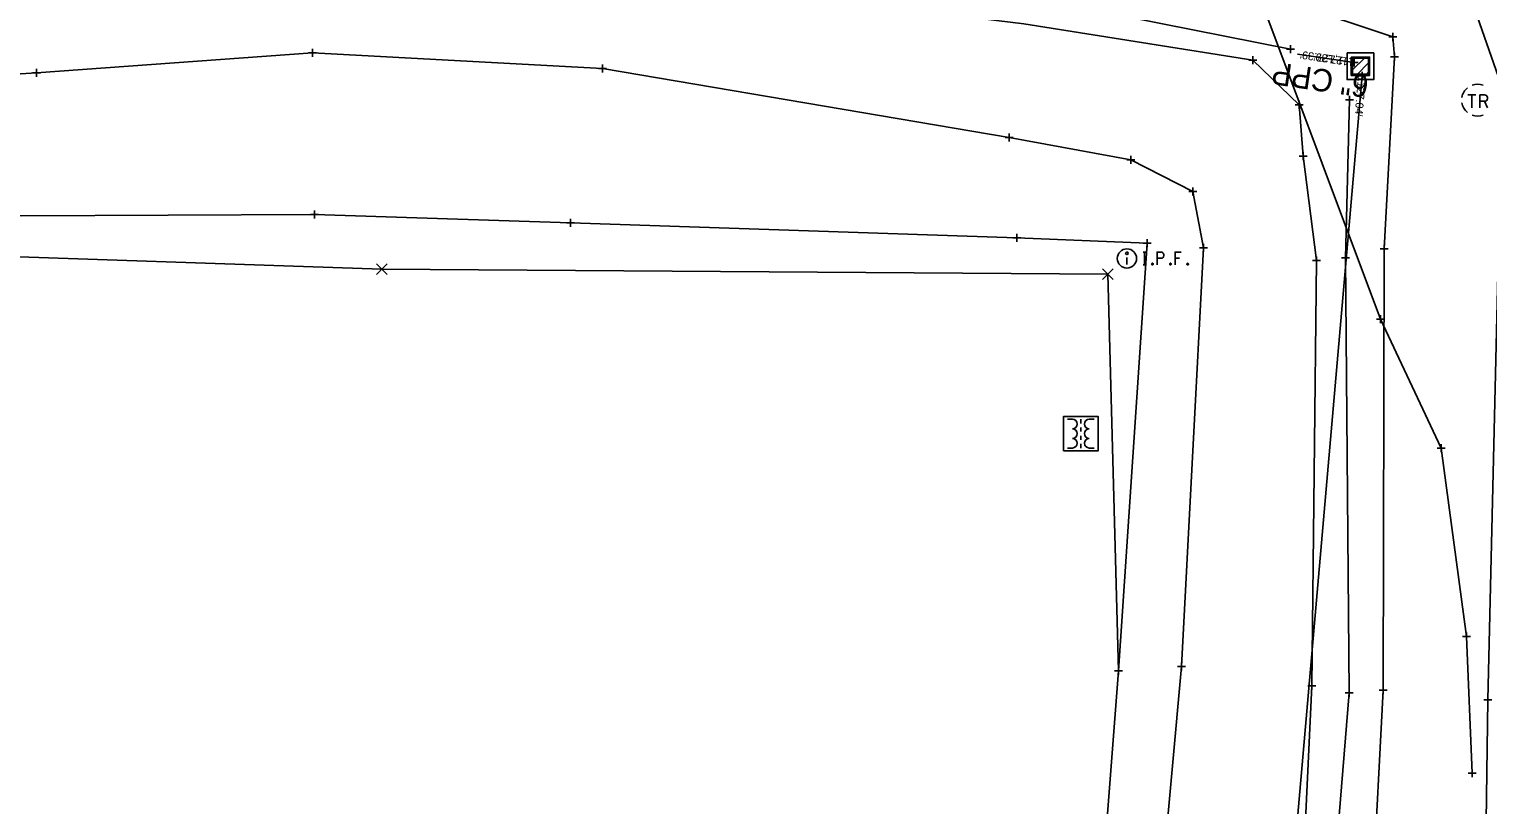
# Model space of a CAD drawing. Extents: x 207090 to 277928, y 600777 to 621109.
# Drawn here: x 260765.1 to 260947.4, y 611469.8 to 611566.6 of the extents above; entities that cross this region are included whole.
import ezdxf

# ---------------------------------------------------------------- set-up
doc = ezdxf.new("R2010")
doc.units = 0
for name, color, linetype in [('ATDIMS', 7, 'Continuous'), ('DR_X_Ditch', 7, 'Continuous'), ('DR_X_Storm_Sewer', 7, 'Continuous'), ('DR_X_Text', 7, 'Continuous'), ('DT_X_Break_Line', 7, 'Continuous'), ('PM_P_Channelizing_Line', 7, 'Continuous'), ('PM_P_Edge_Line', 7, 'Continuous'), ('PM_P_Lane_Line', 7, 'Continuous'), ('PM_P_Stop_Line', 7, 'Continuous'), ('PM_X_Edge_Line', 7, 'Continuous'), ('PM_X_Lane_Line', 7, 'Continuous'), ('PV_X_COP', 7, 'Continuous'), ('SC_ProfileRun1', 7, 'Continuous'), ('SC_ProfileRun2', 7, 'Continuous'), ('SC_ProfileRun4', 7, 'Continuous'), ('SV_X_Terrain_Boundary', 7, 'Continuous'), ('SV_X_Toe_of_Slope', 7, 'Continuous'), ('UT_X_FO', 7, 'Continuous')]:
    doc.layers.add(name, color=color, linetype=linetype)

msp = doc.modelspace()

# ---------------------------------------------------------------- linework, layer by layer
at = {"layer": 'DR_X_Ditch'}
for points in [[(260922.71, 611564.11), (260890.1, 611570.61), (260838.53, 611574.76), (260802.48, 611577.5), (260766.37, 611577.17), (260721.33, 611574.97), (260650.56, 611573.72), (260623.07, 611583.7), (260580.3, 611596.7), (260534.96, 611609.27), (260480.65, 611625.85), (260438.14, 611643.07), (260395.35, 611661.63), (260359.84, 611676.62), (260316.28, 611695.06), (260281.01, 611710.64), (260238.37, 611728.41), (260199.78, 611745.66), (260157.66, 611763.38), (260118.67, 611782.58), (260078.85, 611801.04), (260037.76, 611818.47), (260001.09, 611831.86), (259993.95, 611834.65)], [(260918.27, 611325.53), (260922.87, 611381.19), (260925.97, 611433.7), (260930.02, 611483.73), (260929.59, 611538.06), (260930.07, 611557.8)]]:
    msp.add_lwpolyline(points, dxfattribs=at)
at = {"layer": 'DR_X_Storm_Sewer'}
for p, q in [((260930.64, 611562.44), (260923.59, 611563.47)), ((260931.65, 611560.79), (260881.99, 610991.41))]:
    msp.add_line(p, q, dxfattribs=at)
at = {"layer": 'DT_X_Break_Line'}
msp.add_lwpolyline([(259527, 611849.97), (259626.95, 611842.34), (259741, 611827.05), (259865.07, 611829.81), (259960.08, 611805.1), (260054.94, 611770.89), (260146.45, 611730.46), (260219.24, 611692.26), (260311.2, 611653.27), (260395, 611624.63), (260483.4, 611590.72), (260567.09, 611557.23), (260605.33, 611542.61), (260696.47, 611540.48), (260809.17, 611536.63), (260899.87, 611536.02), (260901.21, 611486.51)], dxfattribs=at)
at = {"layer": 'PM_P_Channelizing_Line'}
msp.add_line((260902.27, 611538.1), (260902.27, 611537.21), dxfattribs=at)
for points in [[(260904.3, 611538.78), (260904.65, 611538.78)], [(260904.47, 611537.18), (260904.47, 611538.78)], [(260906.04, 611537.18), (260906.04, 611538.78), (260906.57, 611538.78), (260906.62, 611538.77), (260906.7, 611538.74), (260906.73, 611538.72), (260906.77, 611538.69), (260906.81, 611538.63), (260906.84, 611538.57), (260906.86, 611538.46), (260906.86, 611538.31), (260906.85, 611538.26), (260906.83, 611538.19), (260906.79, 611538.1), (260906.74, 611538.06), (260906.71, 611538.04), (260906.66, 611538.01), (260906.57, 611538), (260906.04, 611538)], [(260909.05, 611538.78), (260908.29, 611538.78), (260908.29, 611537.18)], [(260904.3, 611537.18), (260904.65, 611537.18)], [(260905.43, 611537.39), (260905.49, 611537.39), (260905.52, 611537.37), (260905.55, 611537.32), (260905.55, 611537.26), (260905.52, 611537.2), (260905.49, 611537.18), (260905.43, 611537.18), (260905.4, 611537.2), (260905.37, 611537.26), (260905.37, 611537.32), (260905.4, 611537.37), (260905.43, 611537.39)], [(260907.68, 611537.39), (260907.74, 611537.39), (260907.77, 611537.37), (260907.8, 611537.32), (260907.8, 611537.26), (260907.77, 611537.2), (260907.74, 611537.18), (260907.68, 611537.18), (260907.65, 611537.2), (260907.61, 611537.26), (260907.61, 611537.32), (260907.65, 611537.37), (260907.68, 611537.39)], [(260908.29, 611538), (260908.83, 611538)], [(260909.83, 611537.39), (260909.89, 611537.39), (260909.92, 611537.37), (260909.95, 611537.32), (260909.95, 611537.26), (260909.92, 611537.2), (260909.89, 611537.18), (260909.83, 611537.18), (260909.8, 611537.2), (260909.76, 611537.26), (260909.76, 611537.32), (260909.8, 611537.37), (260909.83, 611537.39)]]:
    msp.add_lwpolyline(points, dxfattribs=at)
for centre, radius in [((260902.27, 611537.98), 1.2), ((260902.27, 611538.63), 0.16)]:
    msp.add_circle(centre, radius, dxfattribs=at)
at = {"layer": 'PM_P_Edge_Line'}
for points in [[(260944.43, 611323.83), (260943.69, 611379.26), (260946.7, 611434.46), (260947.34, 611482.85), (260948.71, 611539.52), (260949, 611559.8), (260944.27, 611573.28), (260917.08, 611581.04), (260891.62, 611582.9), (260840.92, 611586.72), (260801.33, 611590.08), (260766.71, 611591.61), (260720.99, 611594.21), (260657.85, 611596.52), (260629.18, 611606.07), (260588.39, 611617.67)], [(260898.32, 611326.76), (260901.64, 611381.7), (260904.39, 611435.14), (260909.08, 611487.02), (260911.85, 611539.29), (260910.51, 611546.33), (260902.77, 611550.28), (260887.55, 611553.07), (260836.76, 611561.71), (260800.52, 611563.65), (260766.04, 611561.16), (260720.73, 611558.32), (260646.93, 611559.9), (260619.36, 611566.48), (260576.53, 611581.12)]]:
    msp.add_lwpolyline(points, dxfattribs=at)
at = {"layer": 'PM_P_Lane_Line'}
msp.add_lwpolyline([(260889.23, 611327.21), (260893.26, 611381.88), (260897.37, 611436.68), (260901.21, 611486.51), (260904.78, 611539.89), (260888.53, 611540.57), (260832.74, 611542.44), (260800.78, 611543.46), (260764.2, 611543.3), (260720.99, 611544.95), (260641.05, 611546.87), (260617.29, 611547.1), (260564.97, 611566.43)], dxfattribs=at)
at = {"layer": 'PM_P_Stop_Line'}
for p, q in [((260935.47, 611566.16), (260935.47, 611565.16)), ((260922.71, 611564.61), (260922.71, 611563.61)), ((260934.97, 611565.66), (260935.97, 611565.66)), ((260935.47, 611565.66), (260935.47, 611565.66)), ((260800.02, 611563.65), (260801.02, 611563.65)), ((260800.52, 611564.15), (260800.52, 611563.15)), ((260800.52, 611563.65), (260800.52, 611563.65)), ((260917.48, 611562.73), (260918.48, 611562.73)), ((260917.98, 611563.23), (260917.98, 611562.23)), ((260917.98, 611562.73), (260917.98, 611562.73)), ((260922.21, 611564.11), (260923.21, 611564.11)), ((260922.71, 611564.11), (260922.71, 611564.11)), ((260935.2, 611563.16), (260936.2, 611563.16)), ((260935.7, 611563.66), (260935.7, 611562.66)), ((260935.7, 611563.16), (260935.7, 611563.16)), ((260765.54, 611561.16), (260766.54, 611561.16)), ((260766.04, 611561.66), (260766.04, 611560.66)), ((260766.04, 611561.16), (260766.04, 611561.16)), ((260836.26, 611561.71), (260837.26, 611561.71)), ((260836.76, 611562.21), (260836.76, 611561.21)), ((260836.76, 611561.71), (260836.76, 611561.71)), ((260923.28, 611557.17), (260924.28, 611557.17)), ((260923.78, 611557.67), (260923.78, 611556.67)), ((260923.78, 611557.17), (260923.78, 611557.17)), ((260929.57, 611557.8), (260930.57, 611557.8)), ((260930.07, 611558.3), (260930.07, 611557.3)), ((260930.07, 611557.8), (260930.07, 611557.8)), ((260887.55, 611553.57), (260887.55, 611552.57)), ((260887.05, 611553.07), (260888.05, 611553.07)), ((260887.55, 611553.07), (260887.55, 611553.07)), ((260902.27, 611550.28), (260903.27, 611550.28)), ((260902.77, 611550.78), (260902.77, 611549.78)), ((260902.77, 611550.28), (260902.77, 611550.28)), ((260923.8, 611550.74), (260924.8, 611550.74)), ((260924.3, 611551.24), (260924.3, 611550.24)), ((260924.3, 611550.74), (260924.3, 611550.74)), ((260910.01, 611546.33), (260911.01, 611546.33)), ((260910.51, 611546.83), (260910.51, 611545.83)), ((260910.51, 611546.33), (260910.51, 611546.33)), ((260800.28, 611543.46), (260801.28, 611543.46)), ((260800.78, 611543.96), (260800.78, 611542.96)), ((260800.78, 611543.46), (260800.78, 611543.46)), ((260832.24, 611542.44), (260833.24, 611542.44)), ((260832.74, 611542.94), (260832.74, 611541.94)), ((260832.74, 611542.44), (260832.74, 611542.44)), ((260888.53, 611541.07), (260888.53, 611540.07)), ((260888.03, 611540.57), (260889.03, 611540.57)), ((260888.53, 611540.57), (260888.53, 611540.57)), ((260904.28, 611539.89), (260905.28, 611539.89)), ((260904.78, 611540.39), (260904.78, 611539.39)), ((260904.78, 611539.89), (260904.78, 611539.89)), ((260911.35, 611539.29), (260912.35, 611539.29)), ((260911.85, 611539.79), (260911.85, 611538.79)), ((260911.85, 611539.29), (260911.85, 611539.29)), ((260933.91, 611539.2), (260934.91, 611539.2)), ((260934.41, 611539.7), (260934.41, 611538.7)), ((260934.41, 611539.2), (260934.41, 611539.2)), ((260925.47, 611537.74), (260926.47, 611537.74)), ((260925.97, 611538.24), (260925.97, 611537.24)), ((260925.97, 611537.74), (260925.97, 611537.74)), ((260929.09, 611538.06), (260930.09, 611538.06)), ((260929.59, 611538.56), (260929.59, 611537.56)), ((260929.59, 611538.06), (260929.59, 611538.06)), ((260933.47, 611530.42), (260934.47, 611530.42)), ((260933.97, 611530.92), (260933.97, 611529.92)), ((260933.97, 611530.42), (260933.97, 611530.42)), ((260941.03, 611514.29), (260942.03, 611514.29)), ((260941.53, 611514.79), (260941.53, 611513.79)), ((260941.53, 611514.29), (260941.53, 611514.29)), ((260944.19, 611490.79), (260945.19, 611490.79)), ((260944.69, 611491.29), (260944.69, 611490.29)), ((260944.69, 611490.79), (260944.69, 611490.79)), ((260900.71, 611486.51), (260901.71, 611486.51)), ((260901.21, 611487.01), (260901.21, 611486.01)), ((260901.21, 611486.51), (260901.21, 611486.51)), ((260908.58, 611487.02), (260909.58, 611487.02)), ((260909.08, 611487.52), (260909.08, 611486.52)), ((260909.08, 611487.02), (260909.08, 611487.02)), ((260924.88, 611484.61), (260925.88, 611484.61)), ((260925.38, 611485.11), (260925.38, 611484.11)), ((260925.38, 611484.61), (260925.38, 611484.61)), ((260930.02, 611484.23), (260930.02, 611483.23)), ((260934.3, 611484.58), (260934.3, 611483.58)), ((260929.52, 611483.73), (260930.52, 611483.73)), ((260930.02, 611483.73), (260930.02, 611483.73)), ((260933.8, 611484.08), (260934.8, 611484.08)), ((260934.3, 611484.08), (260934.3, 611484.08)), ((260946.84, 611482.85), (260947.84, 611482.85)), ((260947.34, 611483.35), (260947.34, 611482.35)), ((260947.34, 611482.85), (260947.34, 611482.85)), ((260944.89, 611473.72), (260945.89, 611473.72)), ((260945.39, 611474.22), (260945.39, 611473.22)), ((260945.39, 611473.72), (260945.39, 611473.72))]:
    msp.add_line(p, q, dxfattribs=at)
at = {"layer": 'PM_X_Edge_Line'}
for p, q in [((260808.5, 611535.96), (260809.83, 611537.3)), ((260808.5, 611537.3), (260809.83, 611535.96)), ((260899.2, 611535.35), (260900.54, 611536.69)), ((260899.2, 611536.69), (260900.54, 611535.35))]:
    msp.add_line(p, q, dxfattribs=at)
at = {"layer": 'PM_X_Lane_Line'}
msp.add_line((260946.09, 611557.75), (260946.09, 611557.75), dxfattribs=at)
for points in [[(260944.87, 611558.4), (260945.87, 611558.4)], [(260945.37, 611558.4), (260945.37, 611556.8)], [(260946.37, 611556.8), (260946.37, 611558.4), (260946.97, 611558.4), (260947.04, 611558.39), (260947.13, 611558.36), (260947.16, 611558.34), (260947.2, 611558.31), (260947.25, 611558.25), (260947.29, 611558.19), (260947.31, 611558.08), (260947.31, 611557.93), (260947.3, 611557.88), (260947.28, 611557.81), (260947.23, 611557.72), (260947.18, 611557.68), (260947.14, 611557.66), (260947.11, 611557.64), (260947.08, 611557.63), (260946.96, 611557.62), (260946.37, 611557.62)], [(260946.96, 611557.62), (260947.31, 611556.8)]]:
    msp.add_lwpolyline(points, dxfattribs=at)
for start, end in [(130.0806, 170.0721), (70.0577, 110.1061), (190.0169, 230.0392), (250.0577, 290.0473)]:
    msp.add_arc((260946.09, 611557.75), 2, start, end, dxfattribs=at)
at = {"layer": 'PV_X_COP'}
for p, q in [((260894.84, 611517.91), (260895.46, 611517.91)), ((260896.51, 611517.91), (260896.51, 611517.39)), ((260898.18, 611517.91), (260897.56, 611517.91)), ((260896.51, 611516.88), (260896.51, 611516.37)), ((260896.51, 611516.11), (260896.51, 611516.11)), ((260896.51, 611515.85), (260896.51, 611515.34)), ((260894.84, 611514.31), (260895.46, 611514.31)), ((260896.51, 611514.82), (260896.51, 611514.31)), ((260898.18, 611514.31), (260897.56, 611514.31))]:
    msp.add_line(p, q, dxfattribs=at)
msp.add_lwpolyline([(260894.36, 611513.96), (260898.66, 611513.96), (260898.66, 611518.26), (260894.36, 611518.26)], close=True, dxfattribs=at)
for centre, start, end in [((260895.46, 611517.31), 270, 90), ((260897.56, 611517.31), 90, 270), ((260895.46, 611516.11), 270, 90), ((260895.46, 611514.91), 270, 90), ((260897.56, 611516.11), 90, 270), ((260897.56, 611514.91), 90, 270)]:
    msp.add_arc(centre, 0.6, start, end, dxfattribs=at)
at = {"layer": 'SC_ProfileRun1'}
for p, q in [((260930.3, 611561.37), (260932.06, 611563.13)), ((260930.3, 611562.5), (260930.92, 611563.13)), ((260930.89, 611560.83), (260932.59, 611562.53)), ((260932.03, 611560.83), (260932.59, 611561.4))]:
    msp.add_line(p, q, dxfattribs=at)
for points in [[(260929.78, 611563.65), (260933.11, 611563.65), (260933.11, 611560.31), (260929.78, 611560.31)], [(260930.3, 611563.13), (260932.59, 611563.13), (260932.59, 611560.83), (260930.3, 611560.83)], [(260930.44, 611562.98), (260932.44, 611562.98), (260932.44, 611560.98), (260930.44, 611560.98)]]:
    msp.add_lwpolyline(points, close=True, dxfattribs=at)
at = {"layer": 'SC_ProfileRun2'}
for p, q in [((260930.64, 611562.94), (260930.64, 611561.94)), ((260930.14, 611562.44), (260931.14, 611562.44)), ((260930.64, 611562.44), (260930.64, 611562.44)), ((260931.15, 611560.79), (260932.15, 611560.79)), ((260931.65, 611561.29), (260931.65, 611560.29)), ((260931.65, 611560.79), (260931.65, 611560.79))]:
    msp.add_line(p, q, dxfattribs=at)
at = {"layer": 'SC_ProfileRun4'}
for p, q in [((260931.44, 611563.65), (260931.44, 611563.65)), ((260931.44, 611562.98), (260931.44, 611562.98)), ((260930.44, 611561.98), (260930.44, 611561.98)), ((260931.44, 611561.98), (260931.44, 611561.98)), ((260931.44, 611561.98), (260931.44, 611561.98)), ((260931.44, 611561.98), (260931.44, 611561.98)), ((260931.44, 611560.98), (260931.44, 611560.98)), ((260932.44, 611561.98), (260932.44, 611561.98)), ((260931.44, 611560.31), (260931.44, 611560.31))]:
    msp.add_line(p, q, dxfattribs=at)
at = {"layer": 'SV_X_Terrain_Boundary'}
msp.add_lwpolyline([(259960.08, 611805.1), (260054.94, 611770.89), (260146.45, 611730.46), (260219.24, 611692.26), (260311.2, 611653.27), (260395, 611624.63), (260483.4, 611590.72), (260567.09, 611557.23), (260605.33, 611542.61), (260696.47, 611540.48), (260809.17, 611536.63), (260899.87, 611536.02), (260901.21, 611486.51), (260897.37, 611436.68), (260893.26, 611381.88), (260887.57, 611336.25), (260889.23, 611327.21), (260898.32, 611326.76), (260915.52, 611324.45), (260918.27, 611325.53), (260925.91, 611325.5), (260944.43, 611323.83), (260949.14, 611332.66)], dxfattribs=at)
at = {"layer": 'SV_X_Toe_of_Slope'}
for points in [[(260925.91, 611325.5), (260928.03, 611380.05), (260931.69, 611434.61), (260934.3, 611484.08), (260934.41, 611539.2), (260935.7, 611563.16), (260935.47, 611565.66), (260923.1, 611569.78), (260890.28, 611574.12), (260838.78, 611578.45), (260801.76, 611580.16), (260766.16, 611581.37), (260720.99, 611577.37), (260652.11, 611577.24), (260623.87, 611586.69), (260580.98, 611599.92)], [(260915.52, 611324.45), (260919.13, 611381.5), (260922.9, 611432.51), (260925.38, 611484.61), (260925.97, 611537.74), (260924.3, 611550.74), (260923.78, 611557.17), (260917.98, 611562.73), (260889.38, 611567.29), (260838.46, 611573.54), (260801.98, 611575.99), (260766.63, 611575.76), (260721.79, 611572.62), (260650.48, 611571.62), (260622.6, 611579.61), (260579.7, 611593.18)]]:
    msp.add_lwpolyline(points, dxfattribs=at)
at = {"layer": 'UT_X_FO'}
msp.add_lwpolyline([(260914.2, 612004.27), (260911.24, 611956.66), (260901.88, 611909.04), (260902.55, 611806.65), (260897.05, 611755.55), (260894.34, 611699.22), (260898.49, 611660.35), (260904.47, 611630.39), (260911.35, 611587.38), (260919.36, 611569.26), (260933.97, 611530.42), (260941.53, 611514.29), (260944.69, 611490.79), (260945.39, 611473.72)], dxfattribs=at)

# ---------------------------------------------------------------- texts
at = {"layer": 'ATDIMS'}
for s, rotation, p in [("1,127.39'", 171.6714, (260929.39, 611563.13)), ("1127.39'", 171.6714, (260930.71, 611562.93)), ("1127.04'", 265.0146, (260931.15, 611560.83))]:
    msp.add_text(s, height=1, rotation=rotation, dxfattribs=at).set_placement(p)
at = {"layer": 'DR_X_Text'}
msp.add_text('6" CPP', height=2.8, rotation=171.6714, dxfattribs=at).set_placement((260932.62, 611560.78))

doc.saveas('drawing.dxf')
